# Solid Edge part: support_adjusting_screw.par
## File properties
Title: Support adjusting screw
Author: Robert a Rhodes jr
Template: Normal.par
Last saved by: Rajat Kamboj
Revision: 12
Application: Solid Edge
Accuracy: 0.99
Material: aluminum
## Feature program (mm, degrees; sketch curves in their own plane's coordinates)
sketch for "unnamed Protrusion 1" plane through (0, 0, 0) normal (0, -1, 0) x-axis (1, 0, 0)
  circle centre (0, 0) radius 38.1
extrude "unnamed Protrusion 1" add finite 584.2 along +normal
sketch for "ExtrudedCutout_1" plane through (0, -521.208, 0) normal (0, -1, 0) x-axis (1, 0, 0)
extrude "ExtrudedCutout_1" cut finite 76.2 along +normal  Plane_Distance = 62.992 mm
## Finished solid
Body 1: solid body, 5 faces, 4 edges, 0 vertices.
  Faces by surface: plane 3, cylinder 2
  Edges by curve: circle 4
Bounding box of the edges (mm): 76.200 x 584.200 x 76.200, from (-38.1, -584.2, -38.1) to (38.1, 0, 38.1).
Cylindrical faces by radius (mm): R25.4 x1, R38.1 x1
Planar faces by outward normal: +y 1, -y 2
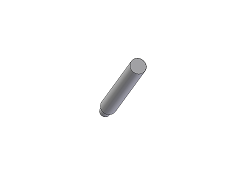
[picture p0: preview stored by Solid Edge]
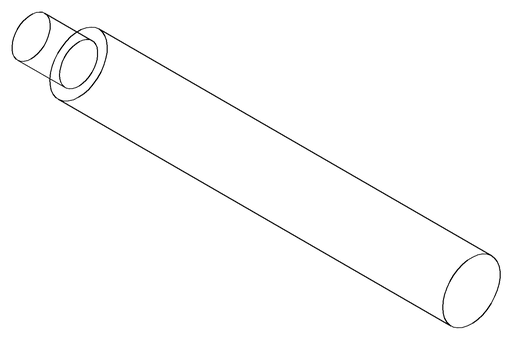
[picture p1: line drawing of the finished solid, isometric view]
